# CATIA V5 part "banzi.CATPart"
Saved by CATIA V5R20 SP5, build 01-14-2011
Part number: 666
Bounding box of the stored display mesh (mm): x -281.475 to 301.525, y -269.949 to 160.051, z 0 to 60
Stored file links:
  C:\Documents and Settings\Student\桌面\zuoping\banzi.CATPart
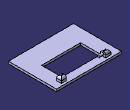
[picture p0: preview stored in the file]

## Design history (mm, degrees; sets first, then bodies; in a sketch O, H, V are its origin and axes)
Body1 (main body)
  Sketch1 on xy-plane, origin (0, 0, 0), H (1, 0, 0), V (0, 1, 0)
    line L1 (-281.4752, 160.0509) -> (301.5248, 160.0509)
    line L2 (301.5248, 160.0509) -> (301.5248, -269.9491)
    line L3 (301.5248, -269.9491) -> (-281.4752, -269.9491)
    line L4 (-281.4752, -269.9491) -> (-281.4752, 160.0509)
    line L5 (-164.4752, 91.8492) -> (184.5248, 91.8492)
    line L6 (184.5248, 91.8492) -> (184.5248, -90.0263)
    line L7 (184.5248, -90.0263) -> (-164.4752, -90.0263)
    line L8 (-164.4752, -90.0263) -> (-164.4752, 91.8492)
    length L1 = 583
    length L4 = 430
    distance L6 L2 = 117
    distance L8 L4 = 117
    horizontal: L1 H, L3 H, L5 H, L7 H
    vertical: L2 V, L4 V, L6 V, L8 V
  Pad1: profile Sketch1, direction (0, 0, 1), length 20
  Sketch2 on end face of Pad1, origin (0, 0, 20), H (1, 0, 0), V (0, 1, 0)
    line L1 (191.5912, 92.8992) -> (236.5912, 92.8992)
    line L2 (236.5912, 92.8992) -> (236.5912, 139.3512)
    line L3 (236.5912, 139.3512) -> (191.5912, 139.3512)
    line L4 (191.5912, 139.3512) -> (191.5912, 92.8992)
    point P5 (-160.1646, 92.8992)
    line L5 (-160.1646, 92.8992) -> (-205.1646, 92.8992)
    line L6 (-205.1646, 92.8992) -> (-205.1646, 139.3512)
    line L7 (-205.1646, 139.3512) -> (-160.1646, 139.3512)
    line L8 (-160.1646, 139.3512) -> (-160.1646, 92.8992)
    point P7 (-205.1646, 139.3512)
    length L3 = 45
    length L7 = 45
    horizontal: L1 H, L3 H, L5 H, L7 H
    vertical: L2 V, L4 V, L6 V, L8 V
    coincidence: P5 L1, P7 L3
  Pad2: profile Sketch2, direction (0, 0, 1), length 40
  Sketch3 on face of Pad2 from Sketch2.L8, origin (-160.1646, 0, 0), H (0, 1, 0), V (0, 0, 1)
    circle A1 centre (116.1372, 38.8126) radius 10
    point P1 (116.1372, 38.8126)
    reference projected line E1 (139.3512, 20) -> (139.3512, 60) from edge [face of Pad2 from Sketch2.L3 | face of Pad2 from Sketch2.L2]
    reference projected line E2 (92.8992, 20) -> (92.8992, 60) from edge [face of Pad2 from Sketch2.L2 | face of Pad2 from Sketch2.L1]
    reference projected line E3 (92.8992, 60) -> (139.3512, 60) from edge [face of Pad2 from Sketch2.L2 | end face of Pad2]
    reference projected line E4 (-269.9491, 20) -> (160.0509, 20) from edge [face of Pad1 from Sketch1.L2 | end face of Pad1]
    distance P1 A1 = 10
    distance E1 E2 = 46.452 (reference)
    distance E3 E4 = 40 (reference)
  Pad3: profile Sketch3, direction (1, 0, 0), length 40
  Fillet1: radius 20, on edge [face of Pad2 from Sketch2.L5 | end face of Pad2]; edge [face of Pad2 from Sketch2.L1 | end face of Pad2]; edge [face of Pad2 from Sketch2.L7 | end face of Pad2]; edge [face of Pad2 from Sketch2.L3 | end face of Pad2]; edge [face of Pad2 from Sketch2.L2 | end face of Pad2]; edge [face of Pad2 from Sketch2.L6 | end face of Pad2]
